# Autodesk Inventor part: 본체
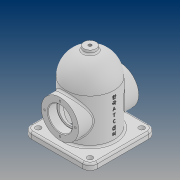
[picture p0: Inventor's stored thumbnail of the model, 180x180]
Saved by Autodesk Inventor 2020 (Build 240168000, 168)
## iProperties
Created: 2021-08
Part Number: 본체
Material: 일반
Document SubType Name: Modeling
Designer: PC312-
Density: 1 g/cm^3
Appearance: 기본값
Mass: 320.708 g
Surface Area: 800.726 cm^2
Volume: 320.708 cm^3
Author: PC312-
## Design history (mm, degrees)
sketch "스케치1"
  geometry: C1 r 40 at (0, 0); 1 further point
  constraints: 1 centre point, 1 coincident
  dimensions: "d0" = 80 diameter of C1
extrude "돌출1" new body sketch "스케치1" distance "d1" = 36; taper "d3" = 0 deg; dims "d2" = 48, "d4" = 0
sketch "스케치2"
  geometry: C1 r 40 at (0, 0); 1 further point
  constraints: 1 centre point, 1 coincident
  dimensions: "d6" = 80 diameter of C1
extrude "돌출2" join sketch "스케치2" distance "d7" = 40; taper "d8" = 0 deg
fillet "모깎기2" dims "d9" = 40
sketch "스케치4"
  geometry: 1 further point
feature "쉘1" dims "d10" = 8
node "작업 평면1"
sketch "스케치5"
  geometry: L1 (-40, -48)-(40, -48) reference; C1 r 31 at (0, 0); 1 further point
  constraints: 1 centre point, 1 coincident
  dimensions: "d29" = 48 distance from line of L1 C1.centre; "d30" = 62 diameter of C1
extrude "돌출5" join sketch "스케치5" stored distance "d31" = 10; taper "d32" = 0 deg
sketch "스케치6"
  geometry: L1 (20, 50)-(20, 35); L2 (20, 35)-(16.5, 35); L3 (16.5, 35)-(16.5, -35); L4 (16.5, -35)-(20, -35); L5 (20, -35)-(20, -50); L6 (0, 71.621)-(0, -88.049); L7 (-48, -32)-(-48, 32) reference; L8 (20, 50)-(0, 50); L9 (20, -50)-(0, -50); L10 (31, 50)-(-31, 50) reference; L11 (31, -50)-(-31, -50) reference; 2 further points
  constraints: 16 end point, 4 horizontal, 4 point on line, 3 vertical, 2 collinear, 1 coincident
  dimensions: "d33" = 48 distance between parallel lines of L7 L6; "d34" = 15 distance between parallel lines of L2 L8; "d35" = 15 distance between parallel lines of L9 L4; "d36" = 40 diameter of L5 L6; "d37" = 33 diameter of L3 L6
revolve "회전3" sketch "스케치6" stored, may be unused: angle "d38" = 90 deg
sketch "스케치7"
  geometry: L1 (55, 55)-(-55, 55); L2 (-55, 55)-(-55, -55); L3 (-55, -55)-(55, -55); L4 (55, -55)-(55, 55); L5 (55, 55)-(-55, -55); L6 (-55, 55)-(55, -55); C1 r 32 at (0, 0) reference; 1 further point
  constraints: 12 end point, 2 midpoint, 2 parallel, 1 horizontal, 1 perpendicular
  dimensions: "d24" = 110 distance between parallel lines of L3 L1; "d25" = 110 distance between parallel lines of L2 L4
extrude "돌출4" join sketch "스케치7" distance "d26" = 10; taper "d27" = 0 deg
fillet "모깎기4" dims "d39" = 0.3
node "작업 평면2"
sketch "스케치8"
  geometry: C1 r 10 at (0, 0); 1 further point
  constraints: 1 centre point, 1 coincident
  dimensions: "d41" = 20 diameter of C1
extrude "돌출6" join sketch "스케치8" stored distance "d42" = 10; taper "d43" = 0 deg
sketch "스케치9"
  geometry: C1 r 10 at (0, 0) reference; 2 further points
  constraints: 1 coincident
hole "구멍1" sketch "스케치9" at (0, 0) diameter "d44" = 5.1881; stored, may be unused: countersink angle "d48" = 90 deg, drill point angle "d50" = 118 deg; dims "d45" = 18, "d46" = 4, "d47" = 2, "d49" = 16
sketch "스케치10"
  geometry: 2 further points
  constraints: 1 vertical alignment
  dimensions: "d51" = 25.5 distance of point (0, 0) point (0, 25.5)
hole "구멍2" sketch "스케치10" at (0, 25.5) diameter "d52" = 3.242; stored, may be unused: countersink angle "d56" = 90 deg, drill point angle "d58" = 118 deg; dims "d53" = 8, "d54" = 4, "d55" = 2, "d57" = 10
fillet "모깎기5" dims "d62" = 12
sketch "스케치11"
  geometry: C1 r 4.5 at (43, 43); C2 r 4.5 at (43, -43); C3 r 4.5 at (-43, -43); C4 r 4.5 at (-43, 43); A1 r 12 centre (43, 43) between (55, 43) and (43, 55) reference; A2 r 12 centre (43, -43) between (43, -55) and (55, -43) reference; A3 r 12 centre (-43, -43) between (-55, -43) and (-43, -55) reference; A4 r 12 centre (-43, 43) between (-43, 55) and (-55, 43) reference; 1 further point
  constraints: 4 centre point, 4 concentric
  dimensions: "d63" = 9 diameter of C1; "d64" = 9 diameter of C2; "d65" = 9 diameter of C3; "d66" = 9 diameter of C4
extrude "돌출7" cut sketch "스케치11" extent not by distance; stored distance "d67" = 0; taper "d68" = 0 deg
node "작업 평면3"
sketch "스케치12" dims "d1" = 36, "d2" = 48, "d3" = 0, "d4" = 0
  geometry: L1 (-48, -43)-(-48, 43) reference; 2 further points
  constraints: 1 other
  dimensions: "d71" = 48 distance from line of L1 point (0, 0); "d72" = 0 distance of point (0, 0) point (0, 0)
feature "엠보싱1" sketch "스케치12" dims "d33" = 48, "d34" = 15, "d35" = 15, "d36" = 40, "d37" = 33, "d73" = 0.5, "d74" = 0
fillet "모깎기6" dims "d75" = 3
fillet "모깎기7" dims "d76" = 3
chamfer "모따기1" distance "d77" = 1; stored, may be unused: second distance "d78" = 2, angle "d79" = 45 deg
node "솔리드1"
mirror "미러1"
pattern_circular "원형 패턴1" dims angle "d60" = 360 deg
mirror "미러2"
feature "A9D066F2-1C7D-4E18-AEED-F7BC21143FA4" dims "d44" = 5.1881, "d45" = 18, "d46" = 4, "d47" = 2, "d48" = 90 deg, "d49" = 16, "d50" = 118 deg
other parameters: "d40" = -129, "d69" = 44.75
